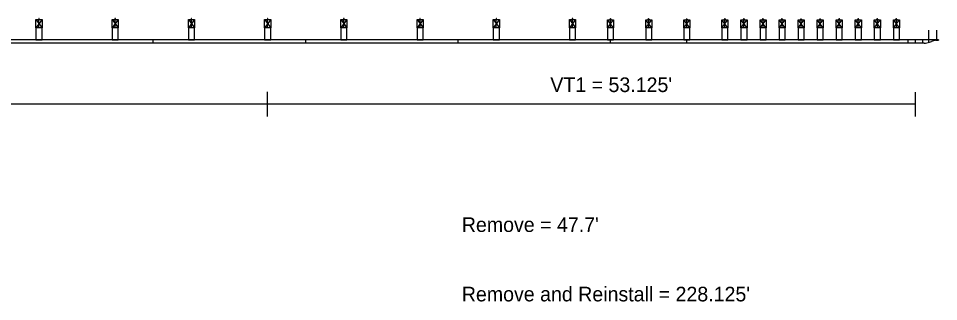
# Model space of a CAD drawing. Extents: x 16537443 to 16538473, y 7054586 to 7055469.
# Drawn here: x 16537885.2 to 16537960.6, y 7054733.4 to 7054756.7 of the extents above; entities that cross this region are included whole.
import ezdxf

# ---------------------------------------------------------------- set-up
doc = ezdxf.new("R2010")
doc.units = 0
doc.layers.add('Draft_DNC', color=7, linetype='Continuous')

msp = doc.modelspace()

# ---------------------------------------------------------------- linework, layer by layer
at = {"layer": 'Draft_DNC'}
for p, q in [((16537887.115, 7054756.553), (16537886.615, 7054755.886)), ((16537886.615, 7054756.553), (16537887.115, 7054755.886)), ((16537886.865, 7054756.65), (16537886.865, 7054756.657)), ((16537886.865, 7054755.886), (16537886.865, 7054756.553)), ((16537893.365, 7054756.553), (16537892.865, 7054755.886)), ((16537892.865, 7054756.553), (16537893.365, 7054755.886)), ((16537893.115, 7054756.65), (16537893.115, 7054756.657)), ((16537893.115, 7054755.886), (16537893.115, 7054756.553)), ((16537899.615, 7054756.553), (16537899.115, 7054755.886)), ((16537899.115, 7054756.553), (16537899.615, 7054755.886)), ((16537899.365, 7054756.65), (16537899.365, 7054756.657)), ((16537899.365, 7054755.886), (16537899.365, 7054756.553)), ((16537905.865, 7054756.553), (16537905.365, 7054755.886)), ((16537905.365, 7054756.553), (16537905.865, 7054755.886)), ((16537905.615, 7054756.65), (16537905.615, 7054756.657)), ((16537905.615, 7054755.886), (16537905.615, 7054756.553)), ((16537912.115, 7054756.553), (16537911.615, 7054755.886)), ((16537911.615, 7054756.553), (16537912.115, 7054755.886)), ((16537911.865, 7054756.65), (16537911.865, 7054756.657)), ((16537911.865, 7054755.886), (16537911.865, 7054756.553)), ((16537918.365, 7054756.553), (16537917.865, 7054755.886)), ((16537917.865, 7054756.553), (16537918.365, 7054755.886)), ((16537918.115, 7054756.65), (16537918.115, 7054756.657)), ((16537918.115, 7054755.886), (16537918.115, 7054756.553)), ((16537924.615, 7054756.553), (16537924.115, 7054755.886)), ((16537924.115, 7054756.553), (16537924.615, 7054755.886)), ((16537924.365, 7054756.65), (16537924.365, 7054756.657)), ((16537924.365, 7054755.886), (16537924.365, 7054756.553)), ((16537930.865, 7054756.553), (16537930.365, 7054755.886)), ((16537930.365, 7054756.553), (16537930.865, 7054755.886)), ((16537930.615, 7054756.65), (16537930.615, 7054756.657)), ((16537930.615, 7054755.886), (16537930.615, 7054756.553)), ((16537933.49, 7054755.885), (16537933.99, 7054756.552)), ((16537933.99, 7054755.885), (16537933.49, 7054756.552)), ((16537933.49, 7054756.552), (16537933.99, 7054756.552)), ((16537933.66, 7054756.552), (16537933.66, 7054756.568)), ((16537933.66, 7054756.568), (16537933.82, 7054756.568)), ((16537933.7, 7054756.568), (16537933.7, 7054756.605)), ((16537933.7, 7054756.605), (16537933.78, 7054756.605)), ((16537933.716, 7054756.568), (16537933.716, 7054756.605)), ((16537933.73, 7054756.605), (16537933.73, 7054756.635)), ((16537933.73, 7054756.635), (16537933.75, 7054756.635)), ((16537933.74, 7054755.885), (16537933.74, 7054756.552)), ((16537933.75, 7054756.605), (16537933.75, 7054756.635)), ((16537933.764, 7054756.568), (16537933.764, 7054756.605)), ((16537933.78, 7054756.568), (16537933.78, 7054756.605)), ((16537933.82, 7054756.552), (16537933.82, 7054756.568)), ((16537936.615, 7054755.885), (16537937.115, 7054756.552)), ((16537937.115, 7054755.885), (16537936.615, 7054756.552)), ((16537936.615, 7054756.552), (16537937.115, 7054756.552)), ((16537936.785, 7054756.552), (16537936.785, 7054756.568)), ((16537936.785, 7054756.568), (16537936.945, 7054756.568)), ((16537936.825, 7054756.568), (16537936.825, 7054756.605)), ((16537936.825, 7054756.605), (16537936.905, 7054756.605)), ((16537936.841, 7054756.568), (16537936.841, 7054756.605)), ((16537936.855, 7054756.605), (16537936.855, 7054756.635)), ((16537936.855, 7054756.635), (16537936.875, 7054756.635)), ((16537936.865, 7054755.885), (16537936.865, 7054756.552)), ((16537936.875, 7054756.605), (16537936.875, 7054756.635)), ((16537936.889, 7054756.568), (16537936.889, 7054756.605)), ((16537936.905, 7054756.568), (16537936.905, 7054756.605)), ((16537936.945, 7054756.552), (16537936.945, 7054756.568)), ((16537939.74, 7054755.885), (16537940.24, 7054756.552)), ((16537940.24, 7054755.885), (16537939.74, 7054756.552)), ((16537939.74, 7054756.552), (16537940.24, 7054756.552)), ((16537939.91, 7054756.552), (16537939.91, 7054756.568)), ((16537939.91, 7054756.568), (16537940.07, 7054756.568)), ((16537939.95, 7054756.568), (16537939.95, 7054756.605)), ((16537939.95, 7054756.605), (16537940.03, 7054756.605)), ((16537939.966, 7054756.568), (16537939.966, 7054756.605)), ((16537939.98, 7054756.605), (16537939.98, 7054756.635)), ((16537939.98, 7054756.635), (16537940, 7054756.635)), ((16537939.99, 7054755.885), (16537939.99, 7054756.552)), ((16537940, 7054756.605), (16537940, 7054756.635)), ((16537940.014, 7054756.568), (16537940.014, 7054756.605)), ((16537940.03, 7054756.568), (16537940.03, 7054756.605)), ((16537940.07, 7054756.552), (16537940.07, 7054756.568)), ((16537942.865, 7054755.885), (16537943.365, 7054756.552)), ((16537943.365, 7054755.885), (16537942.865, 7054756.552)), ((16537942.865, 7054756.552), (16537943.365, 7054756.552)), ((16537943.035, 7054756.552), (16537943.035, 7054756.568)), ((16537943.035, 7054756.568), (16537943.195, 7054756.568)), ((16537943.075, 7054756.568), (16537943.075, 7054756.605)), ((16537943.075, 7054756.605), (16537943.155, 7054756.605)), ((16537943.091, 7054756.568), (16537943.091, 7054756.605)), ((16537943.105, 7054756.605), (16537943.105, 7054756.635)), ((16537943.105, 7054756.635), (16537943.125, 7054756.635)), ((16537943.115, 7054755.885), (16537943.115, 7054756.552)), ((16537943.125, 7054756.605), (16537943.125, 7054756.635)), ((16537943.139, 7054756.568), (16537943.139, 7054756.605)), ((16537943.155, 7054756.568), (16537943.155, 7054756.605)), ((16537943.195, 7054756.552), (16537943.195, 7054756.568)), ((16537944.427, 7054755.885), (16537944.927, 7054756.552)), ((16537944.927, 7054755.885), (16537944.427, 7054756.552)), ((16537944.427, 7054756.552), (16537944.927, 7054756.552)), ((16537944.597, 7054756.552), (16537944.597, 7054756.568)), ((16537944.597, 7054756.568), (16537944.757, 7054756.568)), ((16537944.637, 7054756.568), (16537944.637, 7054756.605)), ((16537944.637, 7054756.605), (16537944.717, 7054756.605)), ((16537944.653, 7054756.568), (16537944.653, 7054756.605)), ((16537944.667, 7054756.605), (16537944.667, 7054756.635)), ((16537944.667, 7054756.635), (16537944.687, 7054756.635)), ((16537944.677, 7054755.885), (16537944.677, 7054756.552)), ((16537944.687, 7054756.605), (16537944.687, 7054756.635)), ((16537944.701, 7054756.568), (16537944.701, 7054756.605)), ((16537944.717, 7054756.568), (16537944.717, 7054756.605)), ((16537944.757, 7054756.552), (16537944.757, 7054756.568)), ((16537945.99, 7054755.885), (16537946.49, 7054756.552)), ((16537946.49, 7054755.885), (16537945.99, 7054756.552)), ((16537945.99, 7054756.552), (16537946.49, 7054756.552)), ((16537946.16, 7054756.552), (16537946.16, 7054756.568)), ((16537946.16, 7054756.568), (16537946.32, 7054756.568)), ((16537946.2, 7054756.568), (16537946.2, 7054756.605)), ((16537946.2, 7054756.605), (16537946.28, 7054756.605)), ((16537946.216, 7054756.568), (16537946.216, 7054756.605)), ((16537946.23, 7054756.605), (16537946.23, 7054756.635)), ((16537946.23, 7054756.635), (16537946.25, 7054756.635)), ((16537946.24, 7054755.885), (16537946.24, 7054756.552)), ((16537946.25, 7054756.605), (16537946.25, 7054756.635)), ((16537946.264, 7054756.568), (16537946.264, 7054756.605)), ((16537946.28, 7054756.568), (16537946.28, 7054756.605)), ((16537946.32, 7054756.552), (16537946.32, 7054756.568)), ((16537947.552, 7054755.885), (16537948.052, 7054756.552)), ((16537948.052, 7054755.885), (16537947.552, 7054756.552)), ((16537947.552, 7054756.552), (16537948.052, 7054756.552)), ((16537947.722, 7054756.552), (16537947.722, 7054756.568)), ((16537947.722, 7054756.568), (16537947.882, 7054756.568)), ((16537947.762, 7054756.568), (16537947.762, 7054756.605)), ((16537947.762, 7054756.605), (16537947.842, 7054756.605)), ((16537947.778, 7054756.568), (16537947.778, 7054756.605)), ((16537947.792, 7054756.605), (16537947.792, 7054756.635)), ((16537947.792, 7054756.635), (16537947.812, 7054756.635)), ((16537947.802, 7054755.885), (16537947.802, 7054756.552)), ((16537947.812, 7054756.605), (16537947.812, 7054756.635)), ((16537947.826, 7054756.568), (16537947.826, 7054756.605)), ((16537947.842, 7054756.568), (16537947.842, 7054756.605)), ((16537947.882, 7054756.552), (16537947.882, 7054756.568)), ((16537949.115, 7054755.885), (16537949.615, 7054756.552)), ((16537949.615, 7054755.885), (16537949.115, 7054756.552)), ((16537949.115, 7054756.552), (16537949.615, 7054756.552)), ((16537949.285, 7054756.552), (16537949.285, 7054756.568)), ((16537949.285, 7054756.568), (16537949.445, 7054756.568)), ((16537949.325, 7054756.568), (16537949.325, 7054756.605)), ((16537949.325, 7054756.605), (16537949.405, 7054756.605)), ((16537949.341, 7054756.568), (16537949.341, 7054756.605)), ((16537949.355, 7054756.605), (16537949.355, 7054756.635)), ((16537949.355, 7054756.635), (16537949.375, 7054756.635)), ((16537949.365, 7054755.885), (16537949.365, 7054756.552)), ((16537949.375, 7054756.605), (16537949.375, 7054756.635)), ((16537949.389, 7054756.568), (16537949.389, 7054756.605)), ((16537949.405, 7054756.568), (16537949.405, 7054756.605)), ((16537949.445, 7054756.552), (16537949.445, 7054756.568)), ((16537950.677, 7054755.885), (16537951.177, 7054756.552)), ((16537951.177, 7054755.885), (16537950.677, 7054756.552)), ((16537950.677, 7054756.552), (16537951.177, 7054756.552)), ((16537950.847, 7054756.552), (16537950.847, 7054756.568)), ((16537950.847, 7054756.568), (16537951.007, 7054756.568)), ((16537950.887, 7054756.568), (16537950.887, 7054756.605)), ((16537950.887, 7054756.605), (16537950.967, 7054756.605)), ((16537950.903, 7054756.568), (16537950.903, 7054756.605)), ((16537950.917, 7054756.605), (16537950.917, 7054756.635)), ((16537950.917, 7054756.635), (16537950.937, 7054756.635)), ((16537950.927, 7054755.885), (16537950.927, 7054756.552)), ((16537950.937, 7054756.605), (16537950.937, 7054756.635)), ((16537950.951, 7054756.568), (16537950.951, 7054756.605)), ((16537950.967, 7054756.568), (16537950.967, 7054756.605)), ((16537951.007, 7054756.552), (16537951.007, 7054756.568)), ((16537952.24, 7054755.885), (16537952.74, 7054756.552)), ((16537952.74, 7054755.885), (16537952.24, 7054756.552)), ((16537952.24, 7054756.552), (16537952.74, 7054756.552)), ((16537952.41, 7054756.552), (16537952.41, 7054756.568)), ((16537952.41, 7054756.568), (16537952.57, 7054756.568)), ((16537952.45, 7054756.568), (16537952.45, 7054756.605)), ((16537952.45, 7054756.605), (16537952.53, 7054756.605)), ((16537952.466, 7054756.568), (16537952.466, 7054756.605)), ((16537952.48, 7054756.605), (16537952.48, 7054756.635)), ((16537952.48, 7054756.635), (16537952.5, 7054756.635)), ((16537952.49, 7054755.885), (16537952.49, 7054756.552)), ((16537952.5, 7054756.605), (16537952.5, 7054756.635)), ((16537952.514, 7054756.568), (16537952.514, 7054756.605)), ((16537952.53, 7054756.568), (16537952.53, 7054756.605)), ((16537952.57, 7054756.552), (16537952.57, 7054756.568)), ((16537953.802, 7054755.885), (16537954.302, 7054756.552)), ((16537954.302, 7054755.885), (16537953.802, 7054756.552)), ((16537953.802, 7054756.552), (16537954.302, 7054756.552)), ((16537953.972, 7054756.552), (16537953.972, 7054756.568)), ((16537953.972, 7054756.568), (16537954.132, 7054756.568)), ((16537954.012, 7054756.568), (16537954.012, 7054756.605)), ((16537954.012, 7054756.605), (16537954.092, 7054756.605)), ((16537954.028, 7054756.568), (16537954.028, 7054756.605)), ((16537954.042, 7054756.605), (16537954.042, 7054756.635)), ((16537954.042, 7054756.635), (16537954.062, 7054756.635)), ((16537954.052, 7054755.885), (16537954.052, 7054756.552)), ((16537954.062, 7054756.605), (16537954.062, 7054756.635)), ((16537954.076, 7054756.568), (16537954.076, 7054756.605)), ((16537954.092, 7054756.568), (16537954.092, 7054756.605)), ((16537954.132, 7054756.552), (16537954.132, 7054756.568)), ((16537955.365, 7054755.885), (16537955.865, 7054756.552)), ((16537955.865, 7054755.885), (16537955.365, 7054756.552)), ((16537955.365, 7054756.552), (16537955.865, 7054756.552)), ((16537955.535, 7054756.552), (16537955.535, 7054756.568)), ((16537955.535, 7054756.568), (16537955.695, 7054756.568)), ((16537955.575, 7054756.568), (16537955.575, 7054756.605)), ((16537955.575, 7054756.605), (16537955.655, 7054756.605)), ((16537955.591, 7054756.568), (16537955.591, 7054756.605)), ((16537955.605, 7054756.605), (16537955.605, 7054756.635)), ((16537955.605, 7054756.635), (16537955.625, 7054756.635)), ((16537955.615, 7054755.885), (16537955.615, 7054756.552)), ((16537955.625, 7054756.605), (16537955.625, 7054756.635)), ((16537955.639, 7054756.568), (16537955.639, 7054756.605)), ((16537955.655, 7054756.568), (16537955.655, 7054756.605)), ((16537955.695, 7054756.552), (16537955.695, 7054756.568)), ((16537956.927, 7054755.885), (16537957.427, 7054756.552)), ((16537957.427, 7054755.885), (16537956.927, 7054756.552)), ((16537956.927, 7054756.552), (16537957.427, 7054756.552)), ((16537957.097, 7054756.552), (16537957.097, 7054756.568)), ((16537957.097, 7054756.568), (16537957.257, 7054756.568)), ((16537957.137, 7054756.568), (16537957.137, 7054756.605)), ((16537957.137, 7054756.605), (16537957.217, 7054756.605)), ((16537957.153, 7054756.568), (16537957.153, 7054756.605)), ((16537957.167, 7054756.605), (16537957.167, 7054756.635)), ((16537957.167, 7054756.635), (16537957.187, 7054756.635)), ((16537957.177, 7054755.885), (16537957.177, 7054756.552)), ((16537957.187, 7054756.605), (16537957.187, 7054756.635)), ((16537957.201, 7054756.568), (16537957.201, 7054756.605)), ((16537957.217, 7054756.568), (16537957.217, 7054756.605)), ((16537957.257, 7054756.552), (16537957.257, 7054756.568)), ((16537887.115, 7054755.886), (16537886.614, 7054755.886)), ((16537886.614, 7054755.886), (16537886.614, 7054754.885)), ((16537887.115, 7054754.885), (16537887.115, 7054755.886)), ((16537893.365, 7054755.886), (16537892.864, 7054755.886)), ((16537892.864, 7054755.886), (16537892.864, 7054754.885)), ((16537893.365, 7054754.885), (16537893.365, 7054755.886)), ((16537899.615, 7054755.886), (16537899.114, 7054755.886)), ((16537899.114, 7054755.886), (16537899.114, 7054754.885)), ((16537899.615, 7054754.885), (16537899.615, 7054755.886)), ((16537905.865, 7054755.886), (16537905.364, 7054755.886)), ((16537905.364, 7054755.886), (16537905.364, 7054754.885)), ((16537905.865, 7054754.885), (16537905.865, 7054755.886)), ((16537912.115, 7054755.886), (16537911.614, 7054755.886)), ((16537911.614, 7054755.886), (16537911.614, 7054754.885)), ((16537912.115, 7054754.885), (16537912.115, 7054755.886)), ((16537918.365, 7054755.886), (16537917.864, 7054755.886)), ((16537917.864, 7054755.886), (16537917.864, 7054754.885)), ((16537918.365, 7054754.885), (16537918.365, 7054755.886)), ((16537924.615, 7054755.886), (16537924.114, 7054755.886)), ((16537924.114, 7054755.886), (16537924.114, 7054754.885)), ((16537924.615, 7054754.885), (16537924.615, 7054755.886)), ((16537930.865, 7054755.886), (16537930.364, 7054755.886)), ((16537930.364, 7054755.886), (16537930.364, 7054754.885)), ((16537930.865, 7054754.885), (16537930.865, 7054755.886)), ((16537933.989, 7054755.885), (16537933.49, 7054755.885)), ((16537933.49, 7054755.885), (16537933.49, 7054754.885)), ((16537933.989, 7054754.885), (16537933.989, 7054755.885)), ((16537937.114, 7054755.885), (16537936.615, 7054755.885)), ((16537936.615, 7054755.885), (16537936.615, 7054754.885)), ((16537937.114, 7054754.885), (16537937.114, 7054755.885)), ((16537940.239, 7054755.885), (16537939.74, 7054755.885)), ((16537939.74, 7054755.885), (16537939.74, 7054754.885)), ((16537940.239, 7054754.885), (16537940.239, 7054755.885)), ((16537943.364, 7054755.885), (16537942.865, 7054755.885)), ((16537942.865, 7054755.885), (16537942.865, 7054754.885)), ((16537943.364, 7054754.885), (16537943.364, 7054755.885)), ((16537944.927, 7054755.885), (16537944.427, 7054755.885)), ((16537944.427, 7054755.885), (16537944.427, 7054754.885)), ((16537944.927, 7054754.885), (16537944.927, 7054755.885)), ((16537946.489, 7054755.885), (16537945.99, 7054755.885)), ((16537945.99, 7054755.885), (16537945.99, 7054754.885)), ((16537946.489, 7054755.885), (16537945.99, 7054755.885)), ((16537945.99, 7054755.885), (16537945.99, 7054754.885)), ((16537946.489, 7054754.885), (16537946.489, 7054755.885)), ((16537946.489, 7054754.885), (16537946.489, 7054755.885)), ((16537948.052, 7054755.885), (16537947.552, 7054755.885)), ((16537947.552, 7054755.885), (16537947.552, 7054754.885)), ((16537948.052, 7054754.885), (16537948.052, 7054755.885)), ((16537949.614, 7054755.885), (16537949.115, 7054755.885)), ((16537949.115, 7054755.885), (16537949.115, 7054754.885)), ((16537949.614, 7054754.885), (16537949.614, 7054755.885)), ((16537951.177, 7054755.885), (16537950.677, 7054755.885)), ((16537950.677, 7054755.885), (16537950.677, 7054754.885)), ((16537951.177, 7054754.885), (16537951.177, 7054755.885)), ((16537952.739, 7054755.885), (16537952.24, 7054755.885)), ((16537952.24, 7054755.885), (16537952.24, 7054754.885)), ((16537952.739, 7054754.885), (16537952.739, 7054755.885)), ((16537954.302, 7054755.885), (16537953.802, 7054755.885)), ((16537953.802, 7054755.885), (16537953.802, 7054754.885)), ((16537954.302, 7054754.885), (16537954.302, 7054755.885)), ((16537955.864, 7054755.885), (16537955.365, 7054755.885)), ((16537955.365, 7054755.885), (16537955.365, 7054754.885)), ((16537955.864, 7054754.885), (16537955.864, 7054755.885)), ((16537957.427, 7054755.885), (16537956.927, 7054755.885)), ((16537956.927, 7054755.885), (16537956.927, 7054754.885)), ((16537957.427, 7054754.885), (16537957.427, 7054755.885)), ((16537959.802, 7054755.677), (16537959.802, 7054754.675)), ((16537960.469, 7054755.677), (16537960.469, 7054754.859)), ((16537896.24, 7054754.885), (16537883.74, 7054754.885)), ((16537896.24, 7054754.615), (16537883.74, 7054754.615)), ((16537886.614, 7054754.885), (16537887.115, 7054754.885)), ((16537892.864, 7054754.885), (16537893.365, 7054754.885)), ((16537896.24, 7054754.615), (16537896.24, 7054754.885)), ((16537908.74, 7054754.885), (16537896.24, 7054754.885)), ((16537896.24, 7054754.615), (16537896.24, 7054754.885)), ((16537908.74, 7054754.615), (16537896.24, 7054754.615)), ((16537899.114, 7054754.885), (16537899.615, 7054754.885)), ((16537905.364, 7054754.885), (16537905.865, 7054754.885)), ((16537908.74, 7054754.615), (16537908.74, 7054754.885)), ((16537921.24, 7054754.885), (16537908.74, 7054754.885)), ((16537908.74, 7054754.615), (16537908.74, 7054754.885)), ((16537921.24, 7054754.615), (16537908.74, 7054754.615)), ((16537911.614, 7054754.885), (16537912.115, 7054754.885)), ((16537917.864, 7054754.885), (16537918.365, 7054754.885)), ((16537921.24, 7054754.615), (16537921.24, 7054754.885)), ((16537921.24, 7054754.615), (16537921.24, 7054754.885)), ((16537960.635, 7054754.885), (16537921.24, 7054754.885)), ((16537959.44, 7054754.615), (16537921.24, 7054754.615)), ((16537924.114, 7054754.885), (16537924.615, 7054754.885)), ((16537930.364, 7054754.885), (16537930.865, 7054754.885)), ((16537933.49, 7054754.885), (16537933.989, 7054754.885)), ((16537933.74, 7054754.615), (16537933.74, 7054754.885)), ((16537959.344, 7054754.615), (16537933.74, 7054754.615)), ((16537936.615, 7054754.885), (16537937.114, 7054754.885)), ((16537939.74, 7054754.885), (16537940.239, 7054754.885)), ((16537939.99, 7054754.615), (16537939.99, 7054754.885)), ((16537942.865, 7054754.885), (16537943.364, 7054754.885)), ((16537944.427, 7054754.885), (16537944.927, 7054754.885)), ((16537945.99, 7054754.885), (16537946.489, 7054754.885)), ((16537945.99, 7054754.885), (16537946.489, 7054754.885)), ((16537947.552, 7054754.885), (16537948.052, 7054754.885)), ((16537949.115, 7054754.885), (16537949.614, 7054754.885)), ((16537950.677, 7054754.885), (16537951.177, 7054754.885)), ((16537952.24, 7054754.885), (16537952.739, 7054754.885)), ((16537953.802, 7054754.885), (16537954.302, 7054754.885)), ((16537955.365, 7054754.885), (16537955.864, 7054754.885)), ((16537956.927, 7054754.885), (16537957.427, 7054754.885)), ((16537958.135, 7054754.615), (16537958.135, 7054754.885)), ((16537958.74, 7054754.615), (16537958.74, 7054754.885)), ((16537959.344, 7054754.615), (16537959.344, 7054754.885)), ((16537959.902, 7054754.708), (16537960.045, 7054754.763)), ((16537960.385, 7054754.86), (16537960.635, 7054754.86)), ((16537960.635, 7054754.885), (16537960.635, 7054754.86)), ((16537905.615, 7054749.616), (16537905.615, 7054750.616)), ((16537958.74, 7054749.615), (16537958.74, 7054750.615)), ((16537905.615, 7054749.616), (16537755.615, 7054749.616)), ((16537958.74, 7054749.615), (16537905.615, 7054749.616)), ((16537905.615, 7054748.616), (16537905.615, 7054749.616)), ((16537958.74, 7054748.615), (16537958.74, 7054749.615))]:
    msp.add_line(p, q, dxfattribs=at)
for points in [[(16537887.115, 7054755.886), (16537886.615, 7054755.886), (16537886.615, 7054756.553), (16537887.115, 7054756.553)], [(16537893.365, 7054755.886), (16537892.865, 7054755.886), (16537892.865, 7054756.553), (16537893.365, 7054756.553)], [(16537899.615, 7054755.886), (16537899.115, 7054755.886), (16537899.115, 7054756.553), (16537899.615, 7054756.553)], [(16537905.865, 7054755.886), (16537905.365, 7054755.886), (16537905.365, 7054756.553), (16537905.865, 7054756.553)], [(16537912.115, 7054755.886), (16537911.615, 7054755.886), (16537911.615, 7054756.553), (16537912.115, 7054756.553)], [(16537918.365, 7054755.886), (16537917.865, 7054755.886), (16537917.865, 7054756.553), (16537918.365, 7054756.553)], [(16537924.615, 7054755.886), (16537924.115, 7054755.886), (16537924.115, 7054756.553), (16537924.615, 7054756.553)], [(16537930.865, 7054755.886), (16537930.365, 7054755.886), (16537930.365, 7054756.553), (16537930.865, 7054756.553)], [(16537933.99, 7054755.885), (16537933.49, 7054755.885), (16537933.49, 7054756.552), (16537933.99, 7054756.552)], [(16537937.115, 7054755.885), (16537936.615, 7054755.885), (16537936.615, 7054756.552), (16537937.115, 7054756.552)], [(16537940.24, 7054755.885), (16537939.74, 7054755.885), (16537939.74, 7054756.552), (16537940.24, 7054756.552)], [(16537943.365, 7054755.885), (16537942.865, 7054755.885), (16537942.865, 7054756.552), (16537943.365, 7054756.552)], [(16537944.927, 7054755.885), (16537944.427, 7054755.885), (16537944.427, 7054756.552), (16537944.927, 7054756.552)], [(16537946.49, 7054755.885), (16537945.99, 7054755.885), (16537945.99, 7054756.552), (16537946.49, 7054756.552)], [(16537948.052, 7054755.885), (16537947.552, 7054755.885), (16537947.552, 7054756.552), (16537948.052, 7054756.552)], [(16537949.615, 7054755.885), (16537949.115, 7054755.885), (16537949.115, 7054756.552), (16537949.615, 7054756.552)], [(16537951.177, 7054755.885), (16537950.677, 7054755.885), (16537950.677, 7054756.552), (16537951.177, 7054756.552)], [(16537952.74, 7054755.885), (16537952.24, 7054755.885), (16537952.24, 7054756.552), (16537952.74, 7054756.552)], [(16537954.302, 7054755.885), (16537953.802, 7054755.885), (16537953.802, 7054756.552), (16537954.302, 7054756.552)], [(16537955.865, 7054755.885), (16537955.365, 7054755.885), (16537955.365, 7054756.552), (16537955.865, 7054756.552)], [(16537957.427, 7054755.885), (16537956.927, 7054755.885), (16537956.927, 7054756.552), (16537957.427, 7054756.552)]]:
    msp.add_lwpolyline(points, close=True, dxfattribs=at)
for points in [[(16537886.898, 7054756.553), (16537886.898, 7054756.596), (16537886.831, 7054756.596), (16537886.831, 7054756.553)], [(16537886.884, 7054756.596), (16537886.884, 7054756.65), (16537886.845, 7054756.65), (16537886.845, 7054756.596)], [(16537893.148, 7054756.553), (16537893.148, 7054756.596), (16537893.081, 7054756.596), (16537893.081, 7054756.553)], [(16537893.134, 7054756.596), (16537893.134, 7054756.65), (16537893.095, 7054756.65), (16537893.095, 7054756.596)], [(16537899.398, 7054756.553), (16537899.398, 7054756.596), (16537899.331, 7054756.596), (16537899.331, 7054756.553)], [(16537899.384, 7054756.596), (16537899.384, 7054756.65), (16537899.345, 7054756.65), (16537899.345, 7054756.596)], [(16537905.648, 7054756.553), (16537905.648, 7054756.596), (16537905.581, 7054756.596), (16537905.581, 7054756.553)], [(16537905.634, 7054756.596), (16537905.634, 7054756.65), (16537905.595, 7054756.65), (16537905.595, 7054756.596)], [(16537911.898, 7054756.553), (16537911.898, 7054756.596), (16537911.831, 7054756.596), (16537911.831, 7054756.553)], [(16537911.884, 7054756.596), (16537911.884, 7054756.65), (16537911.845, 7054756.65), (16537911.845, 7054756.596)], [(16537918.148, 7054756.553), (16537918.148, 7054756.596), (16537918.081, 7054756.596), (16537918.081, 7054756.553)], [(16537918.134, 7054756.596), (16537918.134, 7054756.65), (16537918.095, 7054756.65), (16537918.095, 7054756.596)], [(16537924.398, 7054756.553), (16537924.398, 7054756.596), (16537924.331, 7054756.596), (16537924.331, 7054756.553)], [(16537924.384, 7054756.596), (16537924.384, 7054756.65), (16537924.345, 7054756.65), (16537924.345, 7054756.596)], [(16537930.648, 7054756.553), (16537930.648, 7054756.596), (16537930.581, 7054756.596), (16537930.581, 7054756.553)], [(16537930.634, 7054756.596), (16537930.634, 7054756.65), (16537930.595, 7054756.65), (16537930.595, 7054756.596)]]:
    msp.add_lwpolyline(points, dxfattribs=at)
for centre, major_axis, start_param, end_param in [((16537959.361, 7054756.109), (1.542, 0), 4.763936, 5.071137), ((16537960.597, 7054753.537), (-1.379, 0), 4.866664, 5.124351)]:
    msp.add_ellipse(centre, major_axis=major_axis, ratio=0.97085, start_param=start_param, end_param=end_param, dxfattribs=at)

# ---------------------------------------------------------------- texts
for s, p in [("VT1 = 53.125'", (16537928.796, 7054750.612)), ("Remove = 47.7'", (16537921.538, 7054739.13)), ("Remove and Reinstall = 228.125'", (16537921.538, 7054733.43))]:
    msp.add_text(s, height=1.2, rotation=0.00101, dxfattribs=at).set_placement(p)

doc.saveas('drawing.dxf')
